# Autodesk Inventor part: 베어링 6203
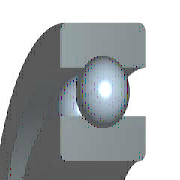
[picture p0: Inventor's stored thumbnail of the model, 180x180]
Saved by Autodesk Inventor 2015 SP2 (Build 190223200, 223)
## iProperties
IsCustomPart: 0
Created: 2009-02
Part Number: 베어링 6203
Material: 강, 연강
Description: 깊은 그루브 볼 베어링
Document SubType Name: Modeling
Standard: KS B 2023
Designer: 한국산업디자인학원 [http://gmhk.co.kr]
Standards Organization: KS
Language: ko-KR
Size Designation: 6203 - 17 x 40 x 12
Categories: <MemberInstance><Categories><Category DisplayName="샤프트 부품" InternalName="7f7aeb1f-a693-4053-b835-cee3144e0d98" Mnemonic="SHFT"><Category DisplayName="베어링" Inter
Density: 7.85 g/cm^3
Appearance: 크롬 - 광택
Mass: 64.8982 g
Surface Area: 64.3582 cm^2
Volume: 8.26729 cm^3
Author: pww
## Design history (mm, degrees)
sketch "스케치" dims "d0" = 5.98 (= -0.26 x WD + 0.26 x BD)
  geometry: L1 (3.01, 14.25)-(8.99, 14.25); L2 (6, 14.25)-(6, 11.26); L3 (6, 14.25)-(6, 17.24); L4 (3.778, 12.249)-(0, 12.249); L5 (0, 8.5)-(12, 8.5); L6 (3.778, 16.251)-(0, 16.251); L7 (0, 20)-(12, 20); L8 (12, 8.5)-(12, 12.249); L9 (8.222, 12.249)-(12, 12.249); L10 (8.222, 16.251)-(12, 16.251); L11 (12, 20)-(12, 16.251); L12 (-1.4, 0)-(8.4, 0) reference; L13 (0, -0.3)-(0, 5.3) reference
  constraints: 22 end point, 4 point on line, 2 collinear, 2 perpendicular, 2 symmetric about line, 1 midpoint, 1 parallel, 14 other
  dimensions: "d9" = 17 diameter of L5 L12 (= WD); "d11" = 40 diameter of L7 L12 (= BD); "d12" = 12 distance between parallel lines of L8 L13 (= KB); "d13" = 24.498 diameter of L9 L12 (= 0.326 x BD + 0.674 x WD)
revolve "본체" stored, may be unused: angle "d6" = 90 deg
revolve "볼" stored, may be unused: angle "d7" = 90 deg
pattern_circular "IDS_ARRAYBALL[SIMPL:T]" dims angle "d3" = 360 deg
body "Solid1"
fillet "모깎기1" dims "d1" = 0.6 (= KRS)
other parameters: "WD" = 17 [user parameter; used in 5 equation terms], "BD" = 40 [user parameter; used in 5 equation terms], "KB" = 12 [user parameter; used in 1 equation term], "KRS" = 0.6 [user parameter; used in 1 equation term], "d4" = 0, "d5" = 0, "d8" = 0, "d14" = 0, "d15" = 0, "BBA" = 0 [user parameter], "BC0" = 4750000 [user parameter], "BC" = 9560000 [user parameter], "WR" = 8.5 (= 0.5 x WD) [user parameter]
